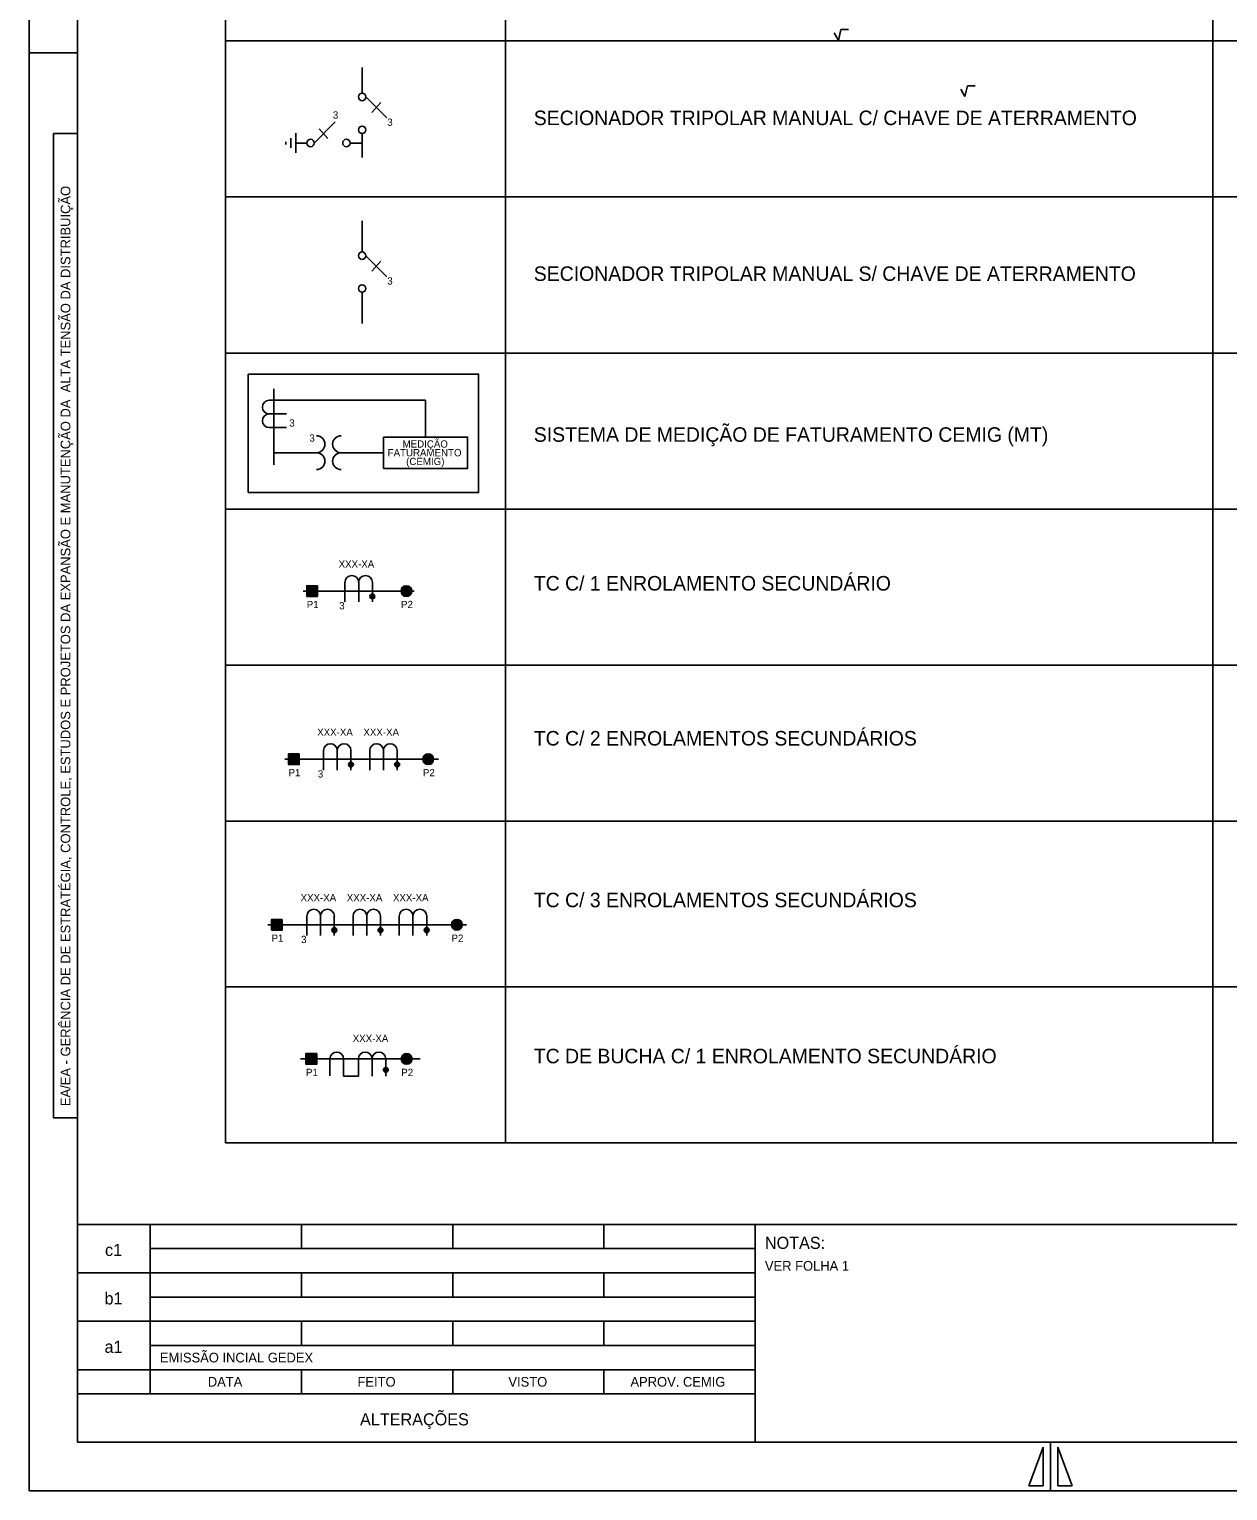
# Model space of a CAD drawing. Extents: x 563 to 3226, y 358 to 960.
# Drawn here: x 1473.9 to 1721.5, y 358 to 659.8 of the extents above; entities that cross this region are included whole.
import ezdxf

# ---------------------------------------------------------------- set-up
doc = ezdxf.new("R2010")
doc.units = 0
for name, color, linetype in [('COMENTÁRIOS_CEMIG_03-12-2019', 7, 'Continuous'), ('Default', 7, 'Continuous'), ('New Level (0)', 7, 'Continuous')]:
    doc.layers.add(name, color=color, linetype=linetype)

# ---------------------------------------------------------------- blocks, each defined once
blk = doc.blocks.new('_U4')
at = {"layer": 'Default'}
for p, q in [((-1.47, 0.42), (-0.62, -1.12)), ((-0.62, -1.12), (-0.07, 1.12)), ((-0.07, 1.12), (1.47, 1.12))]:
    blk.add_line(p, q, dxfattribs=at)

msp = doc.modelspace()

# ---------------------------------------------------------------- linework, layer by layer
at = {"layer": 'COMENTÁRIOS_CEMIG_03-12-2019'}
for p, q in [((1531.22, 544.76), (1533.31, 542.66)), ((1531.22, 544.58), (1533.13, 542.66)), ((1531.22, 544.4), (1532.96, 542.66)), ((1531.22, 544.23), (1532.78, 542.66)), ((1531.22, 544.05), (1532.6, 542.66)), ((1531.22, 543.87), (1532.43, 542.66)), ((1531.22, 543.7), (1532.25, 542.66)), ((1531.22, 543.52), (1532.07, 542.66)), ((1531.22, 543.34), (1531.9, 542.66)), ((1531.28, 544.88), (1533.43, 542.72)), ((1531.45, 544.88), (1533.43, 542.9)), ((1531.63, 544.88), (1533.43, 543.08)), ((1531.81, 544.88), (1533.43, 543.25)), ((1531.98, 544.88), (1533.43, 543.43)), ((1532.16, 544.88), (1533.43, 543.61)), ((1532.34, 544.88), (1533.43, 543.78)), ((1532.51, 544.88), (1533.43, 543.96)), ((1532.69, 544.88), (1533.43, 544.14)), ((1532.87, 544.88), (1533.43, 544.31)), ((1533.04, 544.88), (1533.43, 544.49)), ((1533.22, 544.88), (1533.43, 544.67)), ((1533.4, 544.88), (1533.43, 544.84)), ((1531.22, 543.17), (1531.72, 542.66)), ((1531.22, 542.99), (1531.54, 542.66)), ((1531.22, 542.81), (1531.37, 542.66)), ((1527.52, 510.15), (1529.67, 508)), ((1527.69, 510.15), (1529.67, 508.17)), ((1527.87, 510.15), (1529.67, 508.35)), ((1528.05, 510.15), (1529.67, 508.53)), ((1528.22, 510.15), (1529.67, 508.7)), ((1528.4, 510.15), (1529.67, 508.88)), ((1528.58, 510.15), (1529.67, 509.06)), ((1528.75, 510.15), (1529.67, 509.23)), ((1528.93, 510.15), (1529.67, 509.41)), ((1529.11, 510.15), (1529.67, 509.59)), ((1529.29, 510.15), (1529.67, 509.76)), ((1529.46, 510.15), (1529.67, 509.94)), ((1529.64, 510.15), (1529.67, 510.12)), ((1527.46, 510.03), (1529.55, 507.94)), ((1527.46, 509.85), (1529.38, 507.94)), ((1527.46, 509.68), (1529.2, 507.94)), ((1527.46, 509.5), (1529.02, 507.94)), ((1527.46, 509.32), (1528.84, 507.94)), ((1527.46, 509.15), (1528.67, 507.94)), ((1527.46, 508.97), (1528.49, 507.94)), ((1527.46, 508.79), (1528.31, 507.94)), ((1527.46, 508.62), (1528.14, 507.94)), ((1527.46, 508.44), (1527.96, 507.94)), ((1527.46, 508.26), (1527.78, 507.94)), ((1527.46, 508.09), (1527.61, 507.94)), ((1523.94, 475.84), (1526.03, 473.75)), ((1523.94, 475.67), (1525.86, 473.75)), ((1523.94, 475.49), (1525.68, 473.75)), ((1523.94, 475.31), (1525.5, 473.75)), ((1523.94, 475.13), (1525.33, 473.75)), ((1523.94, 474.96), (1525.15, 473.75)), ((1523.94, 474.78), (1524.97, 473.75)), ((1523.94, 474.6), (1524.8, 473.75)), ((1523.94, 474.43), (1524.62, 473.75)), ((1523.94, 474.25), (1524.44, 473.75)), ((1523.94, 474.07), (1524.27, 473.75)), ((1524, 475.96), (1526.15, 473.81)), ((1524.18, 475.96), (1526.15, 473.98)), ((1524.35, 475.96), (1526.15, 474.16)), ((1524.53, 475.96), (1526.15, 474.34)), ((1524.71, 475.96), (1526.15, 474.51)), ((1524.88, 475.96), (1526.15, 474.69)), ((1525.06, 475.96), (1526.15, 474.87)), ((1525.24, 475.96), (1526.15, 475.05)), ((1525.41, 475.96), (1526.15, 475.22)), ((1525.59, 475.96), (1526.15, 475.4)), ((1525.77, 475.96), (1526.15, 475.58)), ((1525.94, 475.96), (1526.15, 475.75)), ((1526.12, 475.96), (1526.15, 475.93)), ((1523.94, 473.9), (1524.09, 473.75)), ((1531.06, 448.12), (1533.15, 446.03)), ((1531.06, 447.95), (1532.98, 446.03)), ((1531.06, 447.77), (1532.8, 446.03)), ((1531.06, 447.59), (1532.62, 446.03)), ((1531.06, 447.42), (1532.45, 446.03)), ((1531.06, 447.24), (1532.27, 446.03)), ((1531.06, 447.06), (1532.09, 446.03)), ((1531.06, 446.89), (1531.92, 446.03)), ((1531.12, 448.24), (1533.27, 446.09)), ((1531.3, 448.24), (1533.27, 446.27)), ((1531.47, 448.24), (1533.27, 446.44)), ((1531.65, 448.24), (1533.27, 446.62)), ((1531.83, 448.24), (1533.27, 446.8)), ((1532, 448.24), (1533.27, 446.97)), ((1532.18, 448.24), (1533.27, 447.15)), ((1532.36, 448.24), (1533.27, 447.33)), ((1532.53, 448.24), (1533.27, 447.5)), ((1532.71, 448.24), (1533.27, 447.68)), ((1532.89, 448.24), (1533.27, 447.86)), ((1533.06, 448.24), (1533.27, 448.03)), ((1533.24, 448.24), (1533.27, 448.21)), ((1531.06, 446.71), (1531.74, 446.03)), ((1531.06, 446.53), (1531.56, 446.03)), ((1531.06, 446.35), (1531.39, 446.03)), ((1531.06, 446.18), (1531.21, 446.03))]:
    msp.add_line(p, q, dxfattribs=at)
for points in [[(1533.43, 544.88), (1533.43, 542.66), (1531.22, 542.66), (1531.22, 544.88)], [(1529.67, 510.15), (1529.67, 507.94), (1527.46, 507.94), (1527.46, 510.15)], [(1526.15, 475.96), (1526.15, 473.75), (1523.94, 473.75), (1523.94, 475.96)], [(1533.27, 448.24), (1533.27, 446.03), (1531.06, 446.03), (1531.06, 448.24)]]:
    msp.add_lwpolyline(points, close=True, dxfattribs=at)
at = {"layer": 'Default'}
for p, q in [((1547.77, 641.48), (1543.43, 645.82)), ((1544.7, 642.64), (1546.5, 644.66)), ((1537.12, 640.65), (1532.78, 636.31)), ((1527.95, 635.29), (1527.95, 637.34)), ((1528.97, 638.36), (1528.97, 634.27)), ((1533.77, 639.26), (1535.57, 637.24)), ((1526.93, 636.55), (1526.93, 636.02)), ((1531.25, 636.31), (1528.97, 636.31)), ((1542.66, 636.31), (1540.18, 636.31)), ((1547.77, 608.7), (1543.43, 613.04)), ((1544.7, 609.86), (1546.5, 611.88)), ((1523.47, 583.2), (1527.01, 583.2)), ((1524.39, 569.81), (1524.39, 585.52)), ((1527.01, 583.2), (1555.78, 583.2)), ((1523.47, 580.37), (1527.01, 580.37)), ((1523.47, 577.54), (1527.01, 577.54)), ((1524.39, 572.35), (1533.22, 572.35)), ((1538.32, 572.35), (1547.11, 572.35)), ((1539.12, 545.55), (1539.12, 541.54)), ((1541.95, 545.55), (1541.95, 541.54)), ((1544.78, 545.55), (1544.78, 541.54)), ((1550.71, 543.85), (1551.89, 542.67)), ((1550.71, 543.65), (1551.69, 542.67)), ((1550.73, 544.02), (1552.06, 542.69)), ((1550.77, 543.39), (1551.43, 542.73)), ((1550.78, 544.17), (1552.21, 542.74)), ((1550.84, 544.3), (1552.34, 542.8)), ((1550.92, 544.42), (1552.46, 542.88)), ((1551.01, 544.53), (1552.57, 542.96)), ((1551.11, 544.62), (1552.66, 543.07)), ((1551.22, 544.7), (1552.75, 543.18)), ((1551.35, 544.77), (1552.82, 543.3)), ((1551.49, 544.83), (1552.87, 543.45)), ((1551.65, 544.86), (1552.91, 543.61)), ((1551.83, 544.88), (1552.92, 543.79)), ((1552.05, 544.85), (1552.89, 544.01)), ((1552.38, 544.72), (1552.76, 544.33)), ((1534.69, 510.83), (1534.69, 506.81)), ((1537.52, 510.83), (1537.52, 506.81)), ((1540.35, 510.83), (1540.35, 506.81)), ((1544.23, 510.83), (1544.23, 506.81)), ((1547.06, 510.83), (1547.06, 506.81)), ((1549.89, 510.83), (1549.89, 506.81)), ((1556.16, 510.14), (1557.42, 508.88)), ((1556.35, 510.15), (1557.43, 509.06)), ((1555.23, 509.12), (1556.41, 507.94)), ((1555.23, 508.92), (1556.21, 507.94)), ((1555.25, 509.29), (1556.58, 507.97)), ((1555.29, 508.67), (1555.95, 508)), ((1555.3, 509.44), (1556.73, 508.01)), ((1555.36, 509.57), (1556.86, 508.07)), ((1555.44, 509.69), (1556.98, 508.15)), ((1555.52, 509.8), (1557.09, 508.24)), ((1555.62, 509.89), (1557.18, 508.34)), ((1555.74, 509.98), (1557.26, 508.45)), ((1555.86, 510.05), (1557.33, 508.58)), ((1556.01, 510.1), (1557.39, 508.72)), ((1556.57, 510.12), (1557.41, 509.28)), ((1556.89, 509.99), (1557.28, 509.61)), ((1531.25, 476.64), (1531.25, 472.63)), ((1534.08, 476.64), (1534.08, 472.63)), ((1536.91, 476.64), (1536.91, 472.63)), ((1540.79, 476.64), (1540.79, 472.63)), ((1543.62, 476.64), (1543.62, 472.63)), ((1546.45, 476.64), (1546.45, 472.63)), ((1550.34, 476.64), (1550.34, 472.63)), ((1553.17, 476.64), (1553.17, 472.63)), ((1556, 476.64), (1556, 472.63)), ((1561.13, 474.93), (1562.31, 473.75)), ((1561.14, 474.73), (1562.11, 473.76)), ((1561.16, 475.1), (1562.48, 473.78)), ((1561.2, 475.25), (1562.63, 473.82)), ((1561.2, 474.48), (1561.86, 473.82)), ((1561.27, 475.39), (1562.77, 473.89)), ((1561.34, 475.51), (1562.89, 473.96)), ((1561.43, 475.61), (1562.99, 474.05)), ((1561.53, 475.71), (1563.09, 474.15)), ((1561.64, 475.79), (1563.17, 474.26)), ((1561.77, 475.86), (1563.24, 474.39)), ((1561.91, 475.91), (1563.29, 474.53)), ((1562.07, 475.95), (1563.33, 474.69)), ((1562.25, 475.96), (1563.34, 474.87)), ((1562.48, 475.93), (1563.31, 475.1)), ((1562.8, 475.81), (1563.19, 475.42)), ((1529.95, 447.13), (1554.67, 447.15)), ((1536.01, 447.14), (1536.01, 443.62)), ((1538.84, 447.14), (1538.84, 443.6)), ((1541.89, 447.14), (1541.89, 443.6)), ((1544.72, 447.14), (1544.72, 443.6)), ((1547.55, 447.14), (1547.55, 443.6)), ((1550.75, 447.21), (1551.93, 446.03)), ((1550.76, 447.01), (1551.73, 446.04)), ((1550.78, 447.38), (1552.1, 446.06)), ((1550.82, 447.53), (1552.25, 446.1)), ((1550.82, 446.76), (1551.48, 446.1)), ((1550.89, 447.67), (1552.39, 446.17)), ((1550.96, 447.79), (1552.51, 446.24)), ((1551.05, 447.89), (1552.61, 446.33)), ((1551.15, 447.99), (1552.71, 446.43)), ((1551.26, 448.07), (1552.79, 446.54)), ((1551.39, 448.14), (1552.86, 446.67)), ((1551.53, 448.19), (1552.91, 446.81)), ((1551.69, 448.23), (1552.95, 446.97)), ((1551.87, 448.24), (1552.96, 447.15)), ((1552.1, 448.22), (1552.94, 447.38)), ((1552.42, 448.09), (1552.81, 447.7)), ((1538.84, 443.6), (1541.89, 443.6))]:
    msp.add_line(p, q, dxfattribs=at)
for centre, radius in [((1542.66, 645.82), 0.768), ((1532.01, 636.31), 0.768), ((1539.41, 636.31), 0.768), ((1542.66, 639.04), 0.768), ((1542.66, 613.04), 0.768), ((1542.66, 606.26), 0.768), ((1551.81, 543.77), 1.11), ((1544.78, 542.67), 0.501), ((1544.78, 542.67), 0.282), ((1556.33, 509.04), 1.11), ((1540.35, 507.94), 0.501), ((1540.35, 507.94), 0.282), ((1549.89, 507.94), 0.501), ((1549.89, 507.94), 0.282), ((1536.91, 473.75), 0.501), ((1536.91, 473.75), 0.282), ((1546.45, 473.75), 0.501), ((1546.45, 473.75), 0.282), ((1556, 473.75), 0.501), ((1556, 473.75), 0.282), ((1562.24, 474.86), 1.11), ((1551.86, 447.14), 1.11), ((1547.55, 444.87), 0.501), ((1547.55, 444.87), 0.282)]:
    msp.add_circle(centre, radius, dxfattribs=at)
for centre, radius, start, end in [((1523.47, 581.78), 1.42, 90, 270), ((1523.47, 578.95), 1.42, 90, 270), ((1533.22, 574.1), 1.75, 270, 90), ((1538.32, 574.1), 1.75, 90, 270), ((1533.22, 570.6), 1.75, 270, 90), ((1538.32, 570.6), 1.75, 90, 270), ((1540.53, 545.55), 1.42, 0, 180), ((1543.36, 545.55), 1.42, 0, 180), ((1536.1, 510.83), 1.42, 0, 180), ((1538.93, 510.83), 1.42, 0, 180), ((1545.65, 510.83), 1.42, 0, 180), ((1548.48, 510.83), 1.42, 0, 180), ((1532.67, 476.64), 1.42, 0, 180), ((1535.5, 476.64), 1.42, 0, 180), ((1542.21, 476.64), 1.42, 0, 180), ((1545.04, 476.64), 1.42, 0, 180), ((1551.75, 476.64), 1.42, 0, 180), ((1554.58, 476.64), 1.42, 0, 180), ((1537.42, 447.14), 1.42, 0, 180), ((1543.3, 447.14), 1.42, 0, 180), ((1546.13, 447.14), 1.42, 0, 180)]:
    msp.add_arc(centre, radius, start, end, dxfattribs=at)
at = {"layer": 'New Level (0)'}
for p, q in [((1473.88, 951.96), (1473.88, 357.96)), ((1473.88, 951.96), (1473.88, 357.96)), ((1483.88, 941.96), (1483.88, 367.96)), ((1483.88, 941.96), (1483.88, 367.96)), ((1572.28, 925.28), (1572.28, 429.83)), ((1514.44, 657.39), (2214.61, 657.39)), ((1473.88, 654.96), (1483.88, 654.96)), ((1542.66, 646.59), (1542.66, 651.9)), ((1478.88, 638.29), (1483.88, 638.29)), ((1478.88, 434.97), (1478.88, 638.29)), ((1542.66, 633.3), (1542.66, 638.27)), ((1514.44, 625.16), (2214.61, 625.16)), ((1542.66, 613.81), (1542.66, 620.25)), ((1542.66, 599.04), (1542.66, 605.49)), ((1514.44, 592.93), (2214.61, 592.93)), ((1555.78, 575.58), (1555.78, 583.2)), ((1514.44, 560.7), (2214.61, 560.7)), ((1530.47, 543.77), (1553.43, 543.77)), ((1514.44, 528.47), (2214.61, 528.47)), ((1514.44, 528.47), (2214.61, 528.47)), ((1526.71, 509.04), (1558.41, 509.04)), ((1514.44, 496.25), (2214.61, 496.25)), ((1523.2, 474.86), (1564.25, 474.86)), ((1514.44, 462.06), (2214.61, 462.06)), ((1483.88, 434.97), (1478.88, 434.97)), ((1514.44, 429.83), (2214.61, 429.83)), ((1483.88, 412.96), (2304.88, 412.96)), ((1498.88, 377.96), (1498.88, 412.96)), ((1530.13, 407.96), (1530.13, 412.96)), ((1561.38, 407.96), (1561.38, 412.96)), ((1592.63, 407.96), (1592.63, 412.96)), ((1623.88, 412.96), (1623.88, 367.96)), ((1498.88, 407.96), (1623.88, 407.96)), ((1483.88, 402.96), (1623.88, 402.96)), ((1530.13, 397.96), (1530.13, 402.96)), ((1561.38, 397.96), (1561.38, 402.96)), ((1592.63, 397.96), (1592.63, 402.96)), ((1498.88, 397.96), (1623.88, 397.96)), ((1483.88, 392.96), (1623.88, 392.96)), ((1530.13, 387.96), (1530.13, 392.96)), ((1561.38, 387.96), (1561.38, 392.96)), ((1592.63, 387.96), (1592.63, 392.96)), ((1498.88, 387.96), (1623.88, 387.96)), ((1483.88, 382.96), (1623.88, 382.96)), ((1530.13, 377.96), (1530.13, 382.96)), ((1561.38, 377.96), (1561.38, 382.96)), ((1592.63, 377.96), (1592.63, 382.96)), ((1483.88, 377.96), (1623.88, 377.96)), ((1483.88, 367.96), (2304.88, 367.96)), ((1483.88, 367.96), (2304.88, 367.96)), ((1680.38, 358.96), (1683.38, 366.96)), ((1683.38, 366.96), (1683.38, 358.96)), ((1684.88, 367.96), (1684.88, 357.96)), ((1686.38, 366.96), (1686.38, 358.96)), ((1689.38, 358.96), (1686.38, 366.96)), ((1473.88, 357.96), (2314.88, 357.96)), ((1473.88, 357.96), (2314.88, 357.96)), ((1683.38, 358.96), (1680.38, 358.96)), ((1686.38, 358.96), (1689.38, 358.96))]:
    msp.add_line(p, q, dxfattribs=at)
for points in [[(1514.44, 915.21), (1718.4, 915.21), (1718.4, 429.83), (1514.44, 429.83)], [(1718.4, 915.21), (1864.53, 915.21), (1864.53, 429.83), (1718.4, 429.83)], [(1519.14, 588.6), (1566.73, 588.6), (1566.73, 564.16), (1519.14, 564.16)], [(1547.11, 575.58), (1564.45, 575.58), (1564.45, 569.11), (1547.11, 569.11)]]:
    msp.add_lwpolyline(points, close=True, dxfattribs=at)

# ---------------------------------------------------------------- block references
at = {"layer": 'Default'}
for p in [(1641.67, 658.61), (1667.84, 647.01)]:
    msp.add_blockref('_U4', p, dxfattribs=at)

# ---------------------------------------------------------------- texts
for s, height, p in [('SECIONADOR TRIPOLAR MANUAL C/ CHAVE DE ATERRAMENTO', 3, (1578.13, 640)), ('3', 1.5, (1536.61, 641.35)), ('3', 1.5, (1547.86, 639.86)), ('SECIONADOR TRIPOLAR MANUAL S/ CHAVE DE ATERRAMENTO', 3, (1578.13, 607.83)), ('3', 1.5, (1547.86, 607.08)), ('3', 1.5, (1527.6, 577.74)), ('SISTEMA DE MEDIÇÃO DE FATURAMENTO CEMIG (MT)', 3, (1578.13, 574.6)), ('3', 1.5, (1531.76, 574.63)), ('MEDIÇÃO', 1.5, (1551.02, 573.4)), ('FATURAMENTO', 1.5, (1547.94, 571.6)), ('(CEMIG)', 1.5, (1551.76, 569.8)), ('TC C/ 1 ENROLAMENTO SECUNDÁRIO', 3, (1578.13, 543.88)), ('P1', 1.5, (1531.22, 540.25)), ('3', 1.5, (1537.93, 539.99)), ('P2', 1.5, (1550.7, 540.25)), ('TC C/ 2 ENROLAMENTOS SECUNDÁRIOS', 3, (1578.13, 511.87)), ('P1', 1.5, (1527.46, 505.52)), ('3', 1.5, (1533.5, 505.26)), ('P2', 1.5, (1555.22, 505.52)), ('TC C/ 3 ENROLAMENTOS SECUNDÁRIOS', 3, (1578.13, 478.47)), ('P1', 1.5, (1523.94, 471.33)), ('3', 1.5, (1530.06, 471.07)), ('P2', 1.5, (1561.13, 471.33)), ('XXX-XA', 1.5, (1540.72, 450.63)), ('TC DE BUCHA C/ 1 ENROLAMENTO SECUNDÁRIO', 3, (1578.13, 446.24)), ('P1', 1.5, (1531.06, 443.61)), ('P2', 1.5, (1550.75, 443.61))]:
    msp.add_text(s, height=height, dxfattribs=at).set_placement(p)
for p in [(1537.81, 548.61), (1533.38, 513.88), (1542.93, 513.88), (1529.95, 479.69), (1539.49, 479.69), (1549.03, 479.69)]:
    msp.add_text('XXX-XA', height=1.5, rotation=360, dxfattribs=at).set_placement(p)
at = {"layer": 'New Level (0)'}
msp.add_text('EA/EA - GERÊNCIA DE DE ESTRATÉGIA, CONTROLE, ESTUDOS E PROJETOS DA EXPANSÃO E MANUTENÇÃO DA  ALTA TENSÃO DA DISTRIBUIÇÃO', height=2, rotation=90, dxfattribs=at).set_placement((1482.38, 437.39))
for s, height, p in [('c1', 2.5, (1489.54, 406.44)), ('NOTAS:', 2.5, (1625.88, 407.91)), ('VER FOLHA 1', 2, (1625.88, 403.41)), ('b1', 2.5, (1489.44, 396.44)), ('a1', 2.5, (1489.44, 386.44)), ('EMISSÃO INCIAL GEDEX', 2, (1500.88, 384.46)), ('DATA', 2, (1510.78, 379.46)), ('FEITO', 2, (1541.7, 379.46)), ('VISTO', 2, (1572.88, 379.46)), ('APROV. CEMIG', 2, (1598.1, 379.46)), ('ALTERAÇÕES', 2.5, (1542.23, 371.46))]:
    msp.add_text(s, height=height, dxfattribs=at).set_placement(p)

doc.saveas('drawing.dxf')
